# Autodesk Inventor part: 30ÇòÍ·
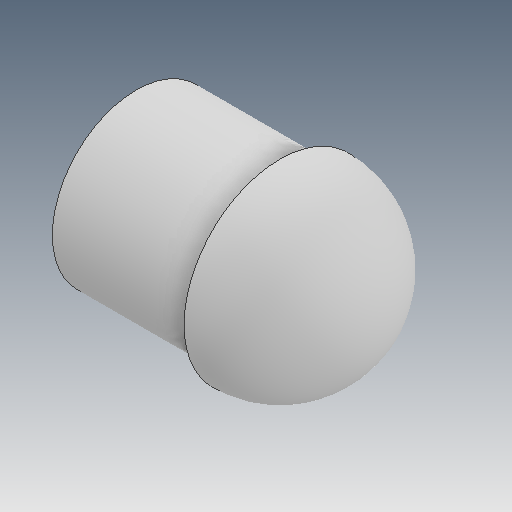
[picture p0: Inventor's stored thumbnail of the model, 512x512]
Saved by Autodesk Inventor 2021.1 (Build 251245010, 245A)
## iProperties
Created: 2019-05
Part Number: 30ÇòÍ·
Material: Ogólny
Document SubType Name: Modeling
Designer: user
Density: 1 g/cm^3
Appearance: Domyślna
Author: user
Revision Number: ÈÎºÎ
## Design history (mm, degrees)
feature "ÊäÈë1"
node "Bryła1"
